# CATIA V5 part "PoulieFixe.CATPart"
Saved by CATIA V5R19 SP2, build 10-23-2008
Part number: PoulieFixe
Bounding box of the stored display mesh (mm): x 0 to 10, y -20 to 20, z -20 to 20
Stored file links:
  D:\SCHOOL\FRANCE\BANC_POUTRE_EN_MOUSSE\PoulieFixe.CATPart
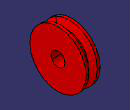
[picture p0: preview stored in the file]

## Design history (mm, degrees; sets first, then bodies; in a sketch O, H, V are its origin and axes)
AxisSystem1: origin (0, 0, 0), X (1, 0, 0), Y (0, 1, 0), Z (0, 0, 1)
Body1 (main body)
  Sketch1 on YZ plane of AxisSystem1, origin (0, 0, 0), H (0, 1, 0), V (0, 0, 1)
    circle A1 centre (0, 0) radius 20
    radius A1 = 20
  Pad1: profile Sketch1, direction (1, 0, 0), length 10
  Sketch2 on ZX plane of AxisSystem1, origin (0, 0, 0), H (0, 0, 1), V (1, 0, 0)
    point P1 (23, 9)
    line L1 (23, 9) -> (15, 6.5)
    point P2 (15, 6.5)
    line L2 (15, 6.5) -> (15, 3.5)
    point P3 (15, 3.5)
    line L3 (15, 3.5) -> (23, 1)
    point P4 (23, 1)
    line L4 (23, 1) -> (23, 9)
    construction line L5 (-7.8383, 5) -> (35.663, 5)
    reference intersected line E1 through (0, 0) direction (-1, 0) from YZ plane of AxisSystem1
    reference intersected line E2 through (0, 0) direction (0, 1) from XY plane of AxisSystem1
    distance E1 L5 = 5
    length L4 = 8
    length L2 = 3
    distance L4 L2 = 8
    distance L2 E2 = 15
    vertical: L2 V, L4 V
    horizontal: L5 H
    symmetry: P2 P3 L5, P1 P4 L5
  Groove1: profile Sketch2, axis axis of face of Pad1 from Sketch1.A1, angle 360
  Sketch3 on start face of Pad1, origin (0, 0, 0), H (0, 1, 0), V (0, 0, -1)
    point P1 (0, 0)
    reference projected point E1 (0, 0) from vertex [YZ plane of AxisSystem1 | ZX plane of AxisSystem1 | XY plane of AxisSystem1]
    coincidence: E1 P1
  Hole1: placed by Sketch3, at (0, 0, 0) direction (1, 0, 0), diameter 10, through (limit type 6)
